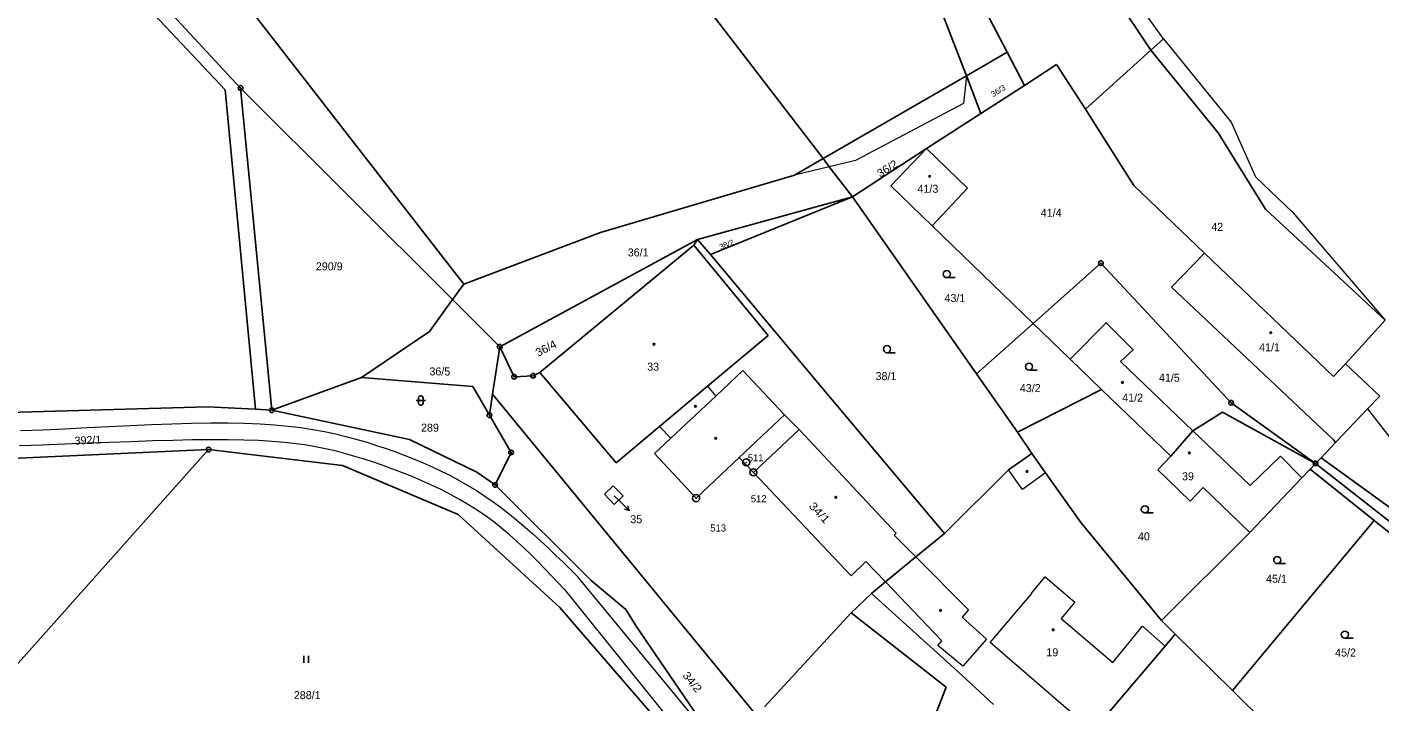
# Model space of a CAD drawing. Extents: x -504006 to -501322, y -1128098 to -1124665.
# Drawn here: x -503112.2 to -502824.9, y -1126660.2 to -1126516.9 of the extents above; entities that cross this region are included whole.
import ezdxf
from ezdxf.enums import TextEntityAlignment as Align

# ---------------------------------------------------------------- set-up
doc = ezdxf.new("R2010")
doc.units = 0
doc.header["$LTSCALE"] = 0.68
for name, color, linetype, lineweight in [('1', 7, 'Continuous', 25), ('3', 7, 'Continuous', 25), ('4', 7, 'Continuous', 13), ('5', 7, 'Continuous', 25), ('7', 7, 'Continuous', 13), ('8', 7, 'Continuous', 25)]:
    doc.layers.add(name, color=color, linetype=linetype, lineweight=lineweight)
doc.layers.add('2', color=7, linetype='Continuous')

msp = doc.modelspace()

# ---------------------------------------------------------------- linework, layer by layer
at = {"layer": '1'}
for p, q in [((-502943.13, -1126544.82), (-502996.74, -1126474.92)), ((-502897.2, -1126486.11), (-502873.53, -1126521.82)), ((-502912.7, -1126527.24), (-502928, -1126487.44)), ((-502921.83, -1126488.04), (-502904.06, -1126522.24)), ((-503019.46, -1126571.46), (-503070.75, -1126505.48)), ((-503086.56, -1126508.57), (-503066.84, -1126529.83)), ((-503088.6, -1126510.51), (-503070.09, -1126530.2)), ((-502904.06, -1126522.24), (-502912.7, -1126527.24)), ((-502904.06, -1126522.24), (-502900.38, -1126529.31)), ((-502887.43, -1126534.31), (-502873.53, -1126521.82)), ((-502873.53, -1126521.82), (-502859.24, -1126539.33)), ((-502900.38, -1126529.31), (-502893.57, -1126524.86)), ((-502893.57, -1126524.86), (-502887.43, -1126534.31)), ((-503066.84, -1126529.83), (-503021.84, -1126574.74)), ((-503060.18, -1126598.23), (-503066.84, -1126529.83)), ((-502943.13, -1126544.82), (-502912.7, -1126527.24)), ((-502912.7, -1126527.24), (-502909.63, -1126535.22)), ((-502909.63, -1126535.22), (-502900.38, -1126529.31)), ((-503070.09, -1126530.2), (-503063.68, -1126598.05)), ((-502884.85, -1126538.34), (-502887.43, -1126534.31)), ((-502884.85, -1126538.34), (-502877.15, -1126550.54)), ((-502859.24, -1126539.33), (-502849.18, -1126555.55)), ((-502936.9, -1126552.95), (-502921.17, -1126542.67)), ((-502928.76, -1126550.63), (-502921.17, -1126542.67)), ((-502949.17, -1126548.31), (-502943.13, -1126544.82)), ((-502941.81, -1126546.55), (-502943.13, -1126544.82)), ((-502936.9, -1126552.95), (-502941.81, -1126546.55)), ((-502990.41, -1126560.5), (-502949.17, -1126548.31)), ((-502969.77, -1126561.97), (-502936.9, -1126552.95)), ((-502967.07, -1126565.19), (-502936.9, -1126552.95)), ((-502936.9, -1126552.95), (-502910.54, -1126590.48)), ((-502919.96, -1126559.12), (-502928.76, -1126550.63)), ((-502877.15, -1126550.54), (-502862.13, -1126564.88)), ((-502849.18, -1126555.55), (-502823.75, -1126579.14)), ((-503019.46, -1126571.46), (-502990.41, -1126560.5)), ((-502898.53, -1126579.8), (-502919.96, -1126559.12)), ((-502969.77, -1126561.97), (-503011.79, -1126584.77)), ((-503003.26, -1126590.23), (-502970.58, -1126563.23)), ((-502970.58, -1126563.23), (-502969.77, -1126561.97)), ((-502970.58, -1126563.23), (-502954.76, -1126582.34)), ((-502969.77, -1126561.97), (-502967.07, -1126565.19)), ((-502967.07, -1126565.19), (-502944.19, -1126592.46)), ((-502884.13, -1126566.99), (-502898.53, -1126579.8)), ((-502862.13, -1126564.88), (-502834.72, -1126591.05)), ((-503019.46, -1126571.46), (-503021.84, -1126574.74)), ((-503021.84, -1126574.74), (-503026.75, -1126581.52)), ((-503021.84, -1126574.74), (-503011.79, -1126584.77)), ((-503026.75, -1126581.52), (-503041.17, -1126591.32)), ((-502890.66, -1126587.4), (-502898.53, -1126579.8)), ((-502823.75, -1126579.14), (-502832.16, -1126588.37)), ((-502954.76, -1126582.34), (-502967.68, -1126593.16)), ((-503013.32, -1126594.85), (-503011.79, -1126584.77)), ((-503011.79, -1126584.77), (-503008.77, -1126591.14)), ((-502884, -1126593.82), (-502890.66, -1126587.4)), ((-503004.74, -1126590.91), (-503003.26, -1126590.23)), ((-502987.1, -1126609.41), (-503003.26, -1126590.23)), ((-502834.72, -1126591.05), (-502832.16, -1126588.37)), ((-502832.16, -1126588.37), (-502824.9, -1126595.25)), ((-503060.18, -1126598.23), (-503041.17, -1126591.32)), ((-503041.17, -1126591.32), (-503017.5, -1126593.2)), ((-503017.5, -1126593.2), (-503014, -1126599.3)), ((-503008.77, -1126591.14), (-503004.74, -1126590.91)), ((-502967.68, -1126593.16), (-502977.9, -1126601.71)), ((-502944.19, -1126592.46), (-502917.37, -1126624.42)), ((-503014, -1126599.3), (-503013.32, -1126594.85)), ((-503013.32, -1126594.85), (-502931.36, -1126694.5)), ((-502901.81, -1126602.9), (-502884, -1126593.82)), ((-502869.29, -1126608.01), (-502884, -1126593.82)), ((-502824.9, -1126595.25), (-502827.48, -1126597.97)), ((-503073.84, -1126597.51), (-503122.52, -1126598.87)), ((-503063.68, -1126598.05), (-503073.84, -1126597.51)), ((-503060.18, -1126598.23), (-503063.68, -1126598.05)), ((-503030.94, -1126604.43), (-503060.18, -1126598.23)), ((-502864.58, -1126602.63), (-502858.29, -1126598.68)), ((-502858.29, -1126598.68), (-502838.52, -1126609.55)), ((-502827.48, -1126597.97), (-502834.28, -1126605.11)), ((-503009.4, -1126607.2), (-503014, -1126599.3)), ((-502977.9, -1126601.71), (-502987.1, -1126609.41)), ((-503016.7, -1126611.4), (-503030.94, -1126604.43)), ((-502901.81, -1126602.9), (-502898.8, -1126607.44)), ((-502869.29, -1126608.01), (-502864.58, -1126602.63)), ((-503147.41, -1126689.3), (-503073.66, -1126606.59)), ((-503121.58, -1126608.76), (-503073.66, -1126606.59)), ((-503073.66, -1126606.59), (-503045.21, -1126610.01)), ((-503012.8, -1126614.1), (-503009.4, -1126607.2)), ((-502898.8, -1126607.44), (-502903.73, -1126610.93)), ((-502895.88, -1126611.55), (-502898.8, -1126607.44)), ((-502834.28, -1126605.11), (-502837.36, -1126608.35)), ((-503045.21, -1126610.01), (-503020.6, -1126620.39)), ((-502872.06, -1126610.88), (-502869.29, -1126608.01)), ((-502838.52, -1126609.55), (-502839.67, -1126610.77)), ((-502837.36, -1126608.35), (-502838.52, -1126609.55)), ((-502838.52, -1126609.55), (-502824.9, -1126620.25)), ((-502786.25, -1126645.31), (-502837.36, -1126608.35)), ((-503012.8, -1126614.1), (-503016.7, -1126611.4)), ((-502903.73, -1126610.93), (-502917.37, -1126624.42)), ((-502888.4, -1126622.06), (-502895.88, -1126611.55)), ((-502865.18, -1126617.54), (-502872.06, -1126610.88)), ((-502841.44, -1126612.62), (-502852.49, -1126624.23)), ((-502992.37, -1126634.4), (-503012.8, -1126614.1)), ((-502989.58, -1126616.09), (-502987.71, -1126614.28)), ((-502987.5, -1126618.29), (-502989.58, -1126616.09)), ((-502987.71, -1126614.28), (-502985.6, -1126616.43)), ((-502862.41, -1126614.66), (-502865.18, -1126617.54)), ((-502852.49, -1126624.23), (-502862.41, -1126614.66)), ((-502985.6, -1126616.43), (-502987.5, -1126618.29)), ((-503020.6, -1126620.39), (-502999.07, -1126640.12)), ((-502856.19, -1126657.72), (-502826.08, -1126621.66)), ((-502806.86, -1126637.06), (-502826.08, -1126621.66)), ((-502824.9, -1126620.25), (-502805.8, -1126635.25)), ((-502917.37, -1126624.42), (-502923.41, -1126629.39)), ((-502871.26, -1126642.9), (-502888.4, -1126622.06)), ((-502852.49, -1126624.23), (-502871.26, -1126642.9)), ((-502923.41, -1126629.39), (-502929.86, -1126634.7)), ((-502985, -1126640.57), (-502992.37, -1126634.4)), ((-502929.86, -1126634.7), (-502932.87, -1126637.18)), ((-502932.87, -1126637.18), (-502937.19, -1126641.28)), ((-502914.51, -1126653.68), (-502932.87, -1126637.18)), ((-502999.07, -1126640.12), (-502973.88, -1126669.24)), ((-502982.84, -1126644.09), (-502985, -1126640.57)), ((-502937.19, -1126641.28), (-502955.59, -1126661.2)), ((-502916.98, -1126657.04), (-502937.19, -1126641.28)), ((-502968.7, -1126664.8), (-502982.84, -1126644.09)), ((-502868.34, -1126645.77), (-502871.26, -1126642.9)), ((-502868.34, -1126645.77), (-502870.5, -1126648.32)), ((-502856.19, -1126657.72), (-502868.34, -1126645.77)), ((-502870.5, -1126648.32), (-502885.81, -1126666.36)), ((-502906.97, -1126660.74), (-502914.51, -1126653.68)), ((-502930.28, -1126691.17), (-502916.98, -1126657.04)), ((-502848.99, -1126664.8), (-502856.19, -1126657.72))]:
    msp.add_line(p, q, dxfattribs=at)
for points in [[(-502919.96, -1126559.12), (-502912.49, -1126551.09), (-502921.17, -1126542.67), (-502909.63, -1126535.22)], [(-502838.52, -1126609.55), (-502856.47, -1126596.66), (-502884.13, -1126566.99)], [(-502834.28, -1126605.11), (-502834.75, -1126604.51), (-502869.1, -1126572.14), (-502862.13, -1126564.88)], [(-502898.53, -1126579.8), (-502910.54, -1126590.48), (-502901.81, -1126602.9)], [(-502890.66, -1126587.4), (-502883.04, -1126579.67), (-502878.22, -1126584.53)], [(-502878.22, -1126584.53), (-502877.26, -1126585.44), (-502879.95, -1126587.92), (-502864.58, -1126602.63)], [(-502826.08, -1126621.66), (-502839.67, -1126610.77), (-502841.44, -1126612.62)]]:
    msp.add_lwpolyline(points, dxfattribs=at)
at = {"layer": '3'}
for p, q in [((-502916.853, -1126570.09), (-502915.103, -1126570.09)), ((-502929.563, -1126586.02), (-502927.813, -1126586.02)), ((-502899.383, -1126589.73), (-502897.633, -1126589.73)), ((-503029.071, -1126595.671), (-503029.071, -1126596.672)), ((-503028.069, -1126596.672), (-503028.069, -1126595.671)), ((-503029.571, -1126596.171), (-503027.569, -1126596.171)), ((-502874.793, -1126620.04), (-502873.043, -1126620.04)), ((-502846.673, -1126630.81), (-502844.923, -1126630.81)), ((-502832.313, -1126646.63), (-502830.563, -1126646.63)), ((-503053.431, -1126651.9), (-503053.431, -1126650.4)), ((-503052.43, -1126651.9), (-503052.43, -1126650.4))]:
    msp.add_line(p, q, dxfattribs=at)
for centre in [(-502916.8529, -1126569.3398), (-502929.5629, -1126585.2698), (-502899.3829, -1126588.9798), (-502874.7929, -1126619.2898), (-502846.6729, -1126630.0598), (-502832.3129, -1126645.8798)]:
    msp.add_circle(centre, 0.75, dxfattribs=at)
for centre, start, end in [((-503028.57, -1126595.6709), 0, 180), ((-503028.57, -1126596.6709), 180, 359.98789)]:
    msp.add_arc(centre, 0.5, start, end, dxfattribs=at)
at = {"layer": '4'}
for p, q in [((-502870.85, -1126519.42), (-502904, -1126472.67)), ((-502873.53, -1126521.82), (-502870.85, -1126519.42)), ((-502870.85, -1126519.42), (-502856.45, -1126537.06)), ((-502912.7, -1126527.24), (-502913.31, -1126533.1)), ((-502913.31, -1126533.1), (-502936.23, -1126545.21)), ((-502856.45, -1126537.06), (-502851.32, -1126548.68)), ((-502941.81, -1126546.55), (-502949.17, -1126548.31)), ((-502936.23, -1126545.21), (-502941.81, -1126546.55)), ((-502851.32, -1126548.68), (-502843.37, -1126556.26)), ((-502843.37, -1126556.26), (-502823.75, -1126579.14)), ((-502965.94, -1126595.23), (-502960.16, -1126589.81)), ((-502960.16, -1126589.81), (-502951.32, -1126599.19)), ((-502967.68, -1126593.16), (-502965.94, -1126595.23)), ((-502975.5, -1126604.19), (-502965.94, -1126595.23)), ((-502827.48, -1126597.97), (-502815.83, -1126613)), ((-502975.5, -1126604.19), (-502977.9, -1126601.71)), ((-502951.32, -1126599.19), (-502960.93, -1126608.26)), ((-502951.32, -1126599.19), (-502948.24, -1126602.34)), ((-502978.97, -1126607.44), (-502975.5, -1126604.19)), ((-502957.93, -1126611.43), (-502948.24, -1126602.34)), ((-502948.24, -1126602.34), (-502927.58, -1126624.32)), ((-502864.58, -1126602.63), (-502852.44, -1126614.24)), ((-502970.1, -1126616.91), (-502978.97, -1126607.44)), ((-502960.93, -1126608.26), (-502970.1, -1126616.91)), ((-502957.93, -1126611.43), (-502960.93, -1126608.26)), ((-502852.44, -1126614.24), (-502845.97, -1126607.96)), ((-502845.97, -1126607.96), (-502841.44, -1126612.62)), ((-502937.17, -1126633.39), (-502957.93, -1126611.43)), ((-502900.81, -1126615.04), (-502903.73, -1126610.93)), ((-502895.88, -1126611.55), (-502900.81, -1126615.04)), ((-502927.58, -1126624.32), (-502928.02, -1126624.74)), ((-502928.02, -1126624.74), (-502923.41, -1126629.39)), ((-502934.04, -1126630.33), (-502937.17, -1126633.39)), ((-502929.86, -1126634.7), (-502934.04, -1126630.33)), ((-502923.41, -1126629.39), (-502912.24, -1126640.64)), ((-502998.05, -1126636.32), (-502972.5, -1126668)), ((-502969.2, -1126665.2), (-502995.2, -1126633.59)), ((-502917.89, -1126647.2), (-502929.86, -1126634.7)), ((-502898.89, -1126637.08), (-502895.95, -1126633.61)), ((-502895.95, -1126633.61), (-502889.65, -1126638.99)), ((-502907.62, -1126647.54), (-502898.81, -1126637.14)), ((-502898.81, -1126637.14), (-502898.89, -1126637.08)), ((-502889.65, -1126638.99), (-502892.59, -1126642.44)), ((-502912.24, -1126640.64), (-502913.58, -1126642.19)), ((-502913.58, -1126642.19), (-502908.42, -1126646.85)), ((-502892.59, -1126642.44), (-502881.62, -1126651.77)), ((-502881.62, -1126651.77), (-502875.3, -1126644.08)), ((-502875.3, -1126644.08), (-502870.5, -1126648.32)), ((-502918.74, -1126648.18), (-502917.89, -1126647.2)), ((-502908.42, -1126646.85), (-502913.46, -1126652.6)), ((-502885.81, -1126666.36), (-502907.62, -1126647.54)), ((-502913.46, -1126652.6), (-502918.74, -1126648.18))]:
    msp.add_line(p, q, dxfattribs=at)
for points in [[(-503113.559, -1126602.578), (-503108.881, -1126602.383), (-503104.19, -1126602.165), (-503099.458, -1126601.932), (-503094.827, -1126601.702), (-503090.27, -1126601.482), (-503085.763, -1126601.28), (-503081.442, -1126601.113), (-503077.282, -1126600.988), (-503073.267, -1126600.916), (-503069.52, -1126600.91), (-503066.014, -1126600.976), (-503062.699, -1126601.116), (-503059.634, -1126601.323), (-503056.76, -1126601.593), (-503054.024, -1126601.928), (-503051.472, -1126602.315), (-503049.051, -1126602.755), (-503046.715, -1126603.25), (-503044.499, -1126603.785), (-503042.355, -1126604.361), (-503040.238, -1126604.982), (-503038.18, -1126605.63), (-503036.139, -1126606.309), (-503034.088, -1126607.029), (-503032.078, -1126607.776), (-503030.087, -1126608.559), (-503028.092, -1126609.392), (-503026.142, -1126610.256), (-503024.215, -1126611.165), (-503022.29, -1126612.131), (-503020.414, -1126613.134), (-503018.566, -1126614.188), (-503016.726, -1126615.308), (-503014.94, -1126616.47), (-503013.186, -1126617.688), (-503011.441, -1126618.975), (-503009.744, -1126620.295), (-503008.072, -1126621.657), (-503006.403, -1126623.075), (-503004.772, -1126624.51), (-503003.158, -1126625.973), (-503001.538, -1126627.478), (-502999.949, -1126628.985), (-502998.368, -1126630.506), (-502996.773, -1126632.055), (-502995.2, -1126633.59)], [(-502998.05, -1126636.32), (-502999.456, -1126634.818), (-503000.885, -1126633.303), (-503002.308, -1126631.814), (-503003.748, -1126630.338), (-503005.228, -1126628.862), (-503006.718, -1126627.425), (-503008.241, -1126626.014), (-503009.821, -1126624.617), (-503011.428, -1126623.271), (-503013.084, -1126621.964), (-503014.817, -1126620.686), (-503016.59, -1126619.47), (-503018.427, -1126618.305), (-503020.345, -1126617.178), (-503022.289, -1126616.115), (-503024.274, -1126615.102), (-503026.313, -1126614.125), (-503028.351, -1126613.208), (-503030.402, -1126612.339), (-503032.483, -1126611.505), (-503034.535, -1126610.727), (-503036.573, -1126609.994), (-503038.614, -1126609.296), (-503040.6, -1126608.65), (-503042.552, -1126608.046), (-503044.516, -1126607.479), (-503046.473, -1126606.964), (-503048.473, -1126606.494), (-503050.57, -1126606.066), (-503052.742, -1126605.691), (-503055.04, -1126605.366), (-503057.524, -1126605.088), (-503060.162, -1126604.866), (-503063.011, -1126604.696), (-503066.135, -1126604.58), (-503069.49, -1126604.52), (-503073.128, -1126604.515), (-503077.075, -1126604.56), (-503081.204, -1126604.647), (-503085.527, -1126604.767), (-503090.067, -1126604.916), (-503094.681, -1126605.083), (-503099.391, -1126605.261), (-503104.221, -1126605.445), (-503109.023, -1126605.625), (-503113.821, -1126605.793)]]:
    msp.add_lwpolyline(points, dxfattribs=at)
at = {"layer": '5'}
for centre in [(-502920.4968, -1126548.5892), (-502848.0468, -1126581.7592), (-502979.0268, -1126584.2192), (-502879.5468, -1126592.3392), (-502970.2368, -1126597.4292), (-502965.9168, -1126604.2192), (-502865.3568, -1126607.2992), (-502899.8068, -1126611.2392), (-502940.4168, -1126616.7292), (-502918.1868, -1126640.7592), (-502894.2568, -1126644.8592)]:
    msp.add_circle(centre, 0.175, dxfattribs=at)
at = {"layer": '7'}
msp.add_line((-502984.211, -1126619.585), (-502984.584, -1126618.529), dxfattribs=at)
msp.add_lwpolyline([(-502987.49, -1126616.41), (-502986.37, -1126617.5), (-502984.211, -1126619.585), (-502985.28, -1126619.249)], dxfattribs=at)
at = {"layer": '8'}
for centre, radius in [((-503066.84, -1126529.8299), 0.5), ((-503066.84, -1126529.8299), 0.0303), ((-502884.13, -1126566.9899), 0.5), ((-502884.13, -1126566.9899), 0.0303), ((-503011.79, -1126584.7699), 0.5), ((-503011.79, -1126584.7699), 0.0303), ((-503008.77, -1126591.1399), 0.5), ((-503008.77, -1126591.1399), 0.0303), ((-503004.74, -1126590.9099), 0.5), ((-503004.74, -1126590.9099), 0.0303), ((-503060.18, -1126598.2299), 0.5), ((-503060.18, -1126598.2299), 0.0303), ((-503014, -1126599.2999), 0.5), ((-502856.47, -1126596.6599), 0.5), ((-502856.47, -1126596.6599), 0.0303), ((-503014, -1126599.2999), 0.0303), ((-503073.66, -1126606.5899), 0.5), ((-503073.66, -1126606.5899), 0.0303), ((-503009.4, -1126607.1999), 0.5), ((-503009.4, -1126607.1999), 0.0303), ((-502959.46, -1126609.3098), 0.75), ((-502959.46, -1126609.3098), 0.03), ((-502838.52, -1126609.5499), 0.5), ((-502838.52, -1126609.5499), 0.0303), ((-502957.93, -1126611.4298), 0.75), ((-502957.93, -1126611.4298), 0.03), ((-503012.8, -1126614.0999), 0.5), ((-503012.8, -1126614.0999), 0.0303), ((-502970.1, -1126616.9098), 0.75), ((-502970.1, -1126616.9098), 0.03)]:
    msp.add_circle(centre, radius, dxfattribs=at)

# ---------------------------------------------------------------- texts
at = {"layer": '2'}
for s, height, rotation, width, p in [('36/3', 1.2, 32, 1.05, (-502905.629, -1126530.9429)), ('36/2', 1.7, 32, 1.05, (-502929.0449, -1126547.6467)), ('36/4', 1.7, 28, 1.05, (-503001.5871, -1126585.8263)), ('34/1', 1.7, 313, 1.15, (-502944.5255, -1126620.5643)), ('34/2', 1.7, 309, 1.1, (-502971.5693, -1126656.4796))]:
    msp.add_text(s, height=height, rotation=rotation, dxfattribs=dict(at, width=width)).set_placement(p, align=Align.CENTER)
for s, p in [('41/3', (-502920.869, -1126552.075)), ('41/4', (-502894.689, -1126557.175)), ('42', (-502859.419, -1126560.155)), ('36/1', (-502982.409, -1126565.585)), ('290/9', (-503048.02, -1126568.545)), ('43/1', (-502915.129, -1126575.272)), ('41/1', (-502848.299, -1126585.715)), ('36/5', (-503024.529, -1126590.855)), ('33', (-502979.219, -1126589.845)), ('38/1', (-502929.769, -1126591.845)), ('43/2', (-502899.129, -1126594.392)), ('41/5', (-502869.589, -1126592.182)), ('41/2', (-502877.389, -1126596.415)), ('289', (-503026.629, -1126602.795)), ('35', (-502982.809, -1126622.235)), ('40', (-502874.999, -1126625.865)), ('45/1', (-502846.829, -1126634.865)), ('19', (-502894.449, -1126650.485)), ('45/2', (-502832.169, -1126650.535)), ('288/1', (-503052.69, -1126659.585))]:
    msp.add_text(s, height=1.7, dxfattribs=at).set_placement(p, align=Align.CENTER)
msp.add_text('38/2', height=1.2, rotation=22, dxfattribs=at).set_placement((-502963.4128, -1126563.6214), align=Align.CENTER)
msp.add_text('392/1', height=1.7, rotation=3, dxfattribs=at).set_placement((-503102.067, -1126605.574))
msp.add_text('39', height=1.7, dxfattribs=at).set_placement((-502866.9, -1126613.115))
at = {"layer": '8'}
for s, p in [('511', (-502955.779, -1126609.077)), ('512', (-502955.139, -1126617.775)), ('513', (-502963.729, -1126623.995))]:
    msp.add_text(s, height=1.5, dxfattribs=at).set_placement(p, align=Align.RIGHT)

doc.saveas('drawing.dxf')
